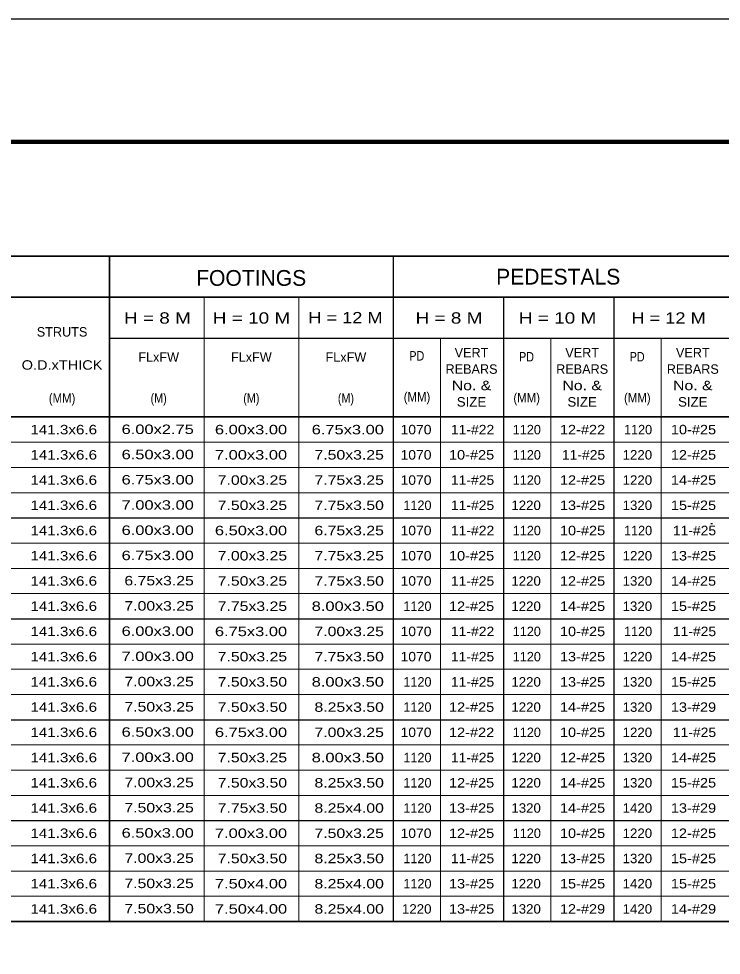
# Model space of a CAD drawing. Extents: x 312601.858 to 312602.699, y 144420.109 to 144420.703.
# Drawn here: x 312602.2619 to 312602.4847, y 144420.4063 to 144420.7033 of the extents above; entities that cross this region are included whole.
import ezdxf
from ezdxf.enums import TextEntityAlignment as Align

# ---------------------------------------------------------------- set-up
doc = ezdxf.new("R2010")
doc.units = 0
doc.header["$LTSCALE"] = 0.0012
doc.layers.add('1', color=7, linetype='Continuous', lineweight=13)
doc.layers.add('39', color=7, linetype='Continuous', lineweight=35)

msp = doc.modelspace()

# ---------------------------------------------------------------- linework, layer by layer
at = {"layer": '1', "lineweight": 35}
for p, q in [((312601.9277, 144420.628), (312602.6681, 144420.628)), ((312602.2907, 144420.417), (312602.2907, 144420.628)), ((312601.9607, 144420.615), (312602.6357, 144420.615)), ((312601.9277, 144420.577), (312602.6681, 144420.577)), ((312601.9277, 144420.417), (312602.6681, 144420.417))]:
    msp.add_line(p, q, dxfattribs=at)
at = {"layer": '1', "lineweight": 25}
for p, q in [((312602.3807, 144420.417), (312602.3807, 144420.628)), ((312602.4157, 144420.417), (312602.4157, 144420.615)), ((312602.4507, 144420.417), (312602.4507, 144420.615)), ((312602.2907, 144420.602), (312602.6357, 144420.602)), ((312601.9609, 144420.545), (312602.6357, 144420.545)), ((312602.4814, 144420.5432), (312602.4819, 144420.5432)), ((312601.9609, 144420.513), (312602.6357, 144420.513)), ((312601.9609, 144420.481), (312602.6357, 144420.481)), ((312601.9609, 144420.449), (312602.6357, 144420.449))]:
    msp.add_line(p, q, dxfattribs=at)
at = {"layer": '1'}
for p, q in [((312602.3207, 144420.417), (312602.3207, 144420.615)), ((312602.3507, 144420.417), (312602.3507, 144420.615)), ((312602.3957, 144420.417), (312602.3957, 144420.602)), ((312602.4307, 144420.417), (312602.4307, 144420.602)), ((312602.4657, 144420.417), (312602.4657, 144420.602)), ((312601.9607, 144420.569), (312602.6357, 144420.569)), ((312601.9609, 144420.561), (312602.6357, 144420.561)), ((312601.9609, 144420.553), (312602.6357, 144420.553)), ((312601.9609, 144420.537), (312602.6357, 144420.537)), ((312601.9609, 144420.529), (312602.6357, 144420.529)), ((312601.9609, 144420.521), (312602.6357, 144420.521)), ((312601.9609, 144420.505), (312602.6357, 144420.505)), ((312601.9609, 144420.497), (312602.6357, 144420.497)), ((312601.9609, 144420.489), (312602.6357, 144420.489)), ((312601.9609, 144420.473), (312602.6357, 144420.473)), ((312601.9609, 144420.465), (312602.6357, 144420.465)), ((312601.9609, 144420.457), (312602.6357, 144420.457)), ((312601.9609, 144420.441), (312602.6357, 144420.441)), ((312601.9609, 144420.433), (312602.6357, 144420.433)), ((312601.9609, 144420.425), (312602.6357, 144420.425))]:
    msp.add_line(p, q, dxfattribs=at)
at = {"layer": '39', "lineweight": 25}
msp.add_line((312601.8579, 144420.7033), (312602.6989, 144420.7033), dxfattribs=at)
at = {"layer": '39', "lineweight": 158}
msp.add_lwpolyline([(312601.9089, 144420.1245), (312601.9089, 144420.6643), (312602.6839, 144420.6643)], dxfattribs=at)

# ---------------------------------------------------------------- texts
at = {"layer": '1'}
for s, height, p in [('FOOTINGS', 0.005, (312602.3356, 144420.6186)), ('PEDESTALS', 0.005, (312602.433, 144420.619)), ('STRUTS', 0.003, (312602.2756, 144420.6025)), ('VERT', 0.003, (312602.4055, 144420.5959)), ('VERT', 0.003, (312602.4406, 144420.5959)), ('VERT', 0.003, (312602.4757, 144420.5959)), ('FLxFW', 0.003, (312602.30625, 144420.5945)), ('FLxFW', 0.003, (312602.33565, 144420.5945)), ('FLxFW', 0.003, (312602.36565, 144420.5945)), ('REBARS', 0.003, (312602.4055, 144420.5907)), ('REBARS', 0.003, (312602.4406, 144420.5907)), ('REBARS', 0.003, (312602.4757, 144420.5907))]:
    msp.add_text(s, height=height, dxfattribs=at).set_placement(p, align=Align.CENTER)
for s, height, width, p in [('H = 8 M', 0.0036, 1.25, (312602.30585, 144420.6066)), ('H = 10 M', 0.0036, 1.25, (312602.3357, 144420.6066)), ('H = 12 M', 0.0036, 1.2, (312602.3655, 144420.6067)), ('H = 8 M', 0.0036, 1.25, (312602.39835, 144420.6066)), ('H = 10 M', 0.0036, 1.25, (312602.4328, 144420.6066)), ('H = 12 M', 0.0036, 1.2, (312602.468, 144420.6066)), ('PD', 0.003, 0.85, (312602.38815, 144420.5949)), ('PD', 0.003, 0.85, (312602.42295, 144420.5946)), ('PD', 0.003, 0.85, (312602.45805, 144420.5946)), ('O.D.xTHICK', 0.003, 1.15, (312602.2756, 144420.592)), ('No. &', 0.003, 1.25, (312602.4055, 144420.5855)), ('No. &', 0.003, 1.25, (312602.4406, 144420.5855)), ('No. &', 0.003, 1.25, (312602.4757, 144420.5855)), ('(MM)', 0.003, 0.9, (312602.2756, 144420.5815)), ('(M)', 0.003, 0.85, (312602.30625, 144420.5815)), ('(M)', 0.003, 0.85, (312602.33565, 144420.5815)), ('(M)', 0.003, 0.85, (312602.36565, 144420.5815)), ('(MM)', 0.003, 0.9, (312602.3882, 144420.5819)), ('SIZE', 0.003, 1.05, (312602.4055, 144420.5803)), ('(MM)', 0.003, 0.9, (312602.423, 144420.5816)), ('SIZE', 0.003, 1.05, (312602.4406, 144420.5803)), ('(MM)', 0.003, 0.9, (312602.4581, 144420.5816)), ('SIZE', 0.003, 1.05, (312602.4757, 144420.5803))]:
    msp.add_text(s, height=height, dxfattribs=dict(at, width=width)).set_placement(p, align=Align.CENTER)
for s, width, p in [('141.3x6.6', 1.2, (312602.2867, 144420.5715)), ('6.00x2.75', 1.3, (312602.3174, 144420.5716)), ('6.00x3.00', 1.3, (312602.347, 144420.5715)), ('6.75x3.00', 1.3, (312602.3777, 144420.5715)), ('1070', 1.1, (312602.3928, 144420.5715)), ('11-#22', 1.1, (312602.4127, 144420.5715)), ('12-#22', 1.15, (312602.4479, 144420.5715)), ('10-#25', 1.15, (312602.4831, 144420.5715)), ('141.3x6.6', 1.2, (312602.2867, 144420.5635)), ('6.50x3.00', 1.3, (312602.3174, 144420.5636)), ('7.00x3.00', 1.3, (312602.347, 144420.5635)), ('7.50x3.25', 1.25, (312602.3777, 144420.5635)), ('1070', 1.1, (312602.3928, 144420.5635)), ('10-#25', 1.15, (312602.4127, 144420.5635)), ('11-#25', 1.1, (312602.4479, 144420.5635)), ('1220', 1.05, (312602.4628, 144420.5635)), ('12-#25', 1.15, (312602.4831, 144420.5635)), ('141.3x6.6', 1.2, (312602.2867, 144420.5555)), ('6.75x3.00', 1.3, (312602.3174, 144420.5556)), ('7.00x3.25', 1.25, (312602.347, 144420.5555)), ('7.75x3.25', 1.25, (312602.3777, 144420.5555)), ('1070', 1.1, (312602.3928, 144420.5555)), ('11-#25', 1.1, (312602.4127, 144420.5555)), ('12-#25', 1.15, (312602.4479, 144420.5555)), ('1220', 1.05, (312602.4628, 144420.5555)), ('14-#25', 1.15, (312602.4831, 144420.5555)), ('7.00x3.00', 1.3, (312602.3174, 144420.5476)), ('141.3x6.6', 1.2, (312602.2867, 144420.5475)), ('7.50x3.25', 1.25, (312602.347, 144420.5475)), ('7.75x3.50', 1.25, (312602.3777, 144420.5475)), ('11-#25', 1.1, (312602.4127, 144420.5475)), ('1220', 1.05, (312602.4275, 144420.5475)), ('13-#25', 1.15, (312602.4479, 144420.5475)), ('1320', 1.05, (312602.4628, 144420.5475)), ('15-#25', 1.15, (312602.4831, 144420.5475)), ('141.3x6.6', 1.2, (312602.2867, 144420.5395)), ('6.00x3.00', 1.3, (312602.3174, 144420.5396)), ('6.50x3.00', 1.3, (312602.347, 144420.5395)), ('6.75x3.25', 1.25, (312602.3777, 144420.5395)), ('1070', 1.1, (312602.3928, 144420.5395)), ('11-#22', 1.1, (312602.4127, 144420.5395)), ('10-#25', 1.15, (312602.4479, 144420.5395)), ('11-#25', 1.1, (312602.4831, 144420.5395)), ('141.3x6.6', 1.2, (312602.2867, 144420.5315)), ('6.75x3.00', 1.3, (312602.3174, 144420.5316)), ('7.00x3.25', 1.25, (312602.347, 144420.5315)), ('7.75x3.25', 1.25, (312602.3777, 144420.5315)), ('1070', 1.1, (312602.3928, 144420.5315)), ('10-#25', 1.15, (312602.4127, 144420.5315)), ('12-#25', 1.15, (312602.4479, 144420.5315)), ('1220', 1.05, (312602.4628, 144420.5315)), ('13-#25', 1.15, (312602.4831, 144420.5315)), ('141.3x6.6', 1.2, (312602.2867, 144420.5235)), ('6.75x3.25', 1.25, (312602.3174, 144420.5236)), ('7.50x3.25', 1.25, (312602.347, 144420.5235)), ('7.75x3.50', 1.25, (312602.3777, 144420.5235)), ('1070', 1.1, (312602.3928, 144420.5235)), ('11-#25', 1.1, (312602.4127, 144420.5235)), ('1220', 1.05, (312602.4275, 144420.5235)), ('12-#25', 1.15, (312602.4479, 144420.5235)), ('1320', 1.05, (312602.4628, 144420.5235)), ('14-#25', 1.15, (312602.4831, 144420.5235)), ('141.3x6.6', 1.2, (312602.2867, 144420.5155)), ('7.00x3.25', 1.25, (312602.3174, 144420.5156)), ('7.75x3.25', 1.25, (312602.347, 144420.5155)), ('8.00x3.50', 1.3, (312602.3777, 144420.5155)), ('12-#25', 1.15, (312602.4127, 144420.5155)), ('1220', 1.05, (312602.4275, 144420.5155)), ('14-#25', 1.15, (312602.4479, 144420.5155)), ('1320', 1.05, (312602.4628, 144420.5155)), ('15-#25', 1.15, (312602.4831, 144420.5155)), ('141.3x6.6', 1.2, (312602.2867, 144420.5075)), ('6.00x3.00', 1.3, (312602.3174, 144420.5076)), ('6.75x3.00', 1.3, (312602.347, 144420.5075)), ('7.00x3.25', 1.25, (312602.3777, 144420.5075)), ('1070', 1.1, (312602.3928, 144420.5075)), ('11-#22', 1.1, (312602.4127, 144420.5075)), ('10-#25', 1.15, (312602.4479, 144420.5075)), ('11-#25', 1.1, (312602.4831, 144420.5075)), ('141.3x6.6', 1.2, (312602.2867, 144420.4995)), ('7.00x3.00', 1.3, (312602.3174, 144420.4996)), ('7.50x3.25', 1.25, (312602.347, 144420.4995)), ('7.75x3.50', 1.25, (312602.3777, 144420.4995)), ('1070', 1.1, (312602.3928, 144420.4995)), ('11-#25', 1.1, (312602.4127, 144420.4995)), ('13-#25', 1.15, (312602.4479, 144420.4995)), ('1220', 1.05, (312602.4628, 144420.4995)), ('14-#25', 1.15, (312602.4831, 144420.4995)), ('141.3x6.6', 1.2, (312602.2867, 144420.4915)), ('7.00x3.25', 1.25, (312602.3174, 144420.4916)), ('7.50x3.50', 1.25, (312602.347, 144420.4915)), ('8.00x3.50', 1.3, (312602.3777, 144420.4915)), ('11-#25', 1.1, (312602.4127, 144420.4915)), ('1220', 1.05, (312602.4275, 144420.4915)), ('13-#25', 1.15, (312602.4479, 144420.4915)), ('1320', 1.05, (312602.4628, 144420.4915)), ('15-#25', 1.15, (312602.4831, 144420.4915)), ('141.3x6.6', 1.2, (312602.2867, 144420.4835)), ('7.50x3.25', 1.25, (312602.3174, 144420.4836)), ('7.50x3.50', 1.25, (312602.347, 144420.4835)), ('8.25x3.50', 1.25, (312602.3777, 144420.4835)), ('12-#25', 1.15, (312602.4127, 144420.4835)), ('1220', 1.05, (312602.4275, 144420.4835)), ('14-#25', 1.15, (312602.4479, 144420.4835)), ('1320', 1.05, (312602.4628, 144420.4835)), ('13-#29', 1.15, (312602.4831, 144420.4835)), ('141.3x6.6', 1.2, (312602.2867, 144420.4755)), ('6.50x3.00', 1.3, (312602.3174, 144420.4756)), ('6.75x3.00', 1.3, (312602.347, 144420.4755)), ('7.00x3.25', 1.25, (312602.3777, 144420.4755)), ('1070', 1.1, (312602.3928, 144420.4755)), ('12-#22', 1.15, (312602.4127, 144420.4755)), ('10-#25', 1.15, (312602.4479, 144420.4755)), ('1220', 1.05, (312602.4628, 144420.4755)), ('11-#25', 1.1, (312602.4831, 144420.4755)), ('141.3x6.6', 1.2, (312602.2867, 144420.4675)), ('7.00x3.00', 1.3, (312602.3174, 144420.4676)), ('7.50x3.25', 1.25, (312602.347, 144420.4675)), ('8.00x3.50', 1.3, (312602.3777, 144420.4675)), ('11-#25', 1.1, (312602.4127, 144420.4675)), ('1220', 1.05, (312602.4275, 144420.4675)), ('12-#25', 1.15, (312602.4479, 144420.4675)), ('1320', 1.05, (312602.4628, 144420.4675)), ('14-#25', 1.15, (312602.4831, 144420.4675)), ('141.3x6.6', 1.2, (312602.2867, 144420.4595)), ('7.00x3.25', 1.25, (312602.3174, 144420.4596)), ('7.50x3.50', 1.25, (312602.347, 144420.4595)), ('8.25x3.50', 1.25, (312602.3777, 144420.4595)), ('12-#25', 1.15, (312602.4127, 144420.4595)), ('1220', 1.05, (312602.4275, 144420.4595)), ('14-#25', 1.15, (312602.4479, 144420.4595)), ('1320', 1.05, (312602.4628, 144420.4595)), ('15-#25', 1.15, (312602.4831, 144420.4595)), ('141.3x6.6', 1.2, (312602.2867, 144420.4515)), ('7.50x3.25', 1.25, (312602.3174, 144420.4516)), ('7.75x3.50', 1.25, (312602.347, 144420.4515)), ('8.25x4.00', 1.25, (312602.3777, 144420.4515)), ('13-#25', 1.15, (312602.4127, 144420.4515)), ('1320', 1.05, (312602.4275, 144420.4515)), ('14-#25', 1.15, (312602.4479, 144420.4515)), ('1420', 1.05, (312602.4628, 144420.4515)), ('13-#29', 1.15, (312602.4831, 144420.4515)), ('6.50x3.00', 1.3, (312602.3174, 144420.4436)), ('141.3x6.6', 1.2, (312602.2867, 144420.4435)), ('7.00x3.00', 1.3, (312602.347, 144420.4435)), ('7.50x3.25', 1.25, (312602.3777, 144420.4435)), ('1070', 1.1, (312602.3928, 144420.4435)), ('12-#25', 1.15, (312602.4127, 144420.4435)), ('10-#25', 1.15, (312602.4479, 144420.4435)), ('1220', 1.05, (312602.4628, 144420.4435)), ('12-#25', 1.15, (312602.4831, 144420.4435)), ('141.3x6.6', 1.2, (312602.2867, 144420.4355)), ('7.00x3.25', 1.25, (312602.3174, 144420.4356)), ('7.50x3.50', 1.25, (312602.347, 144420.4355)), ('8.25x3.50', 1.25, (312602.3777, 144420.4355)), ('11-#25', 1.1, (312602.4127, 144420.4355)), ('1220', 1.05, (312602.4275, 144420.4355)), ('13-#25', 1.15, (312602.4479, 144420.4355)), ('1320', 1.05, (312602.4628, 144420.4355)), ('15-#25', 1.15, (312602.4831, 144420.4355)), ('141.3x6.6', 1.2, (312602.2867, 144420.4275)), ('7.50x3.25', 1.25, (312602.3174, 144420.4276)), ('7.50x4.00', 1.3, (312602.347, 144420.4275)), ('8.25x4.00', 1.25, (312602.3777, 144420.4275)), ('13-#25', 1.15, (312602.4127, 144420.4275)), ('1220', 1.05, (312602.4275, 144420.4275)), ('15-#25', 1.15, (312602.4479, 144420.4275)), ('1420', 1.05, (312602.4628, 144420.4275)), ('15-#25', 1.15, (312602.4831, 144420.4275)), ('141.3x6.6', 1.2, (312602.2867, 144420.4195)), ('7.50x3.50', 1.25, (312602.3174, 144420.4196)), ('7.50x4.00', 1.3, (312602.347, 144420.4195)), ('8.25x4.00', 1.25, (312602.3777, 144420.4195)), ('1220', 1.05, (312602.3928, 144420.4195)), ('13-#25', 1.15, (312602.4127, 144420.4195)), ('1320', 1.05, (312602.4275, 144420.4195)), ('12-#29', 1.15, (312602.4479, 144420.4195)), ('1420', 1.05, (312602.4628, 144420.4195)), ('14-#29', 1.15, (312602.4831, 144420.4195))]:
    msp.add_text(s, height=0.003, dxfattribs=dict(at, width=width)).set_placement(p, align=Align.RIGHT)
for p in [(312602.4275, 144420.5715), (312602.4628, 144420.5715), (312602.4275, 144420.5635), (312602.4275, 144420.5555), (312602.3928, 144420.5475), (312602.4275, 144420.5395), (312602.4628, 144420.5395), (312602.4275, 144420.5315), (312602.3928, 144420.5155), (312602.4275, 144420.5075), (312602.4628, 144420.5075), (312602.4275, 144420.4995), (312602.3928, 144420.4915), (312602.3928, 144420.4835), (312602.4275, 144420.4755), (312602.3928, 144420.4675), (312602.3928, 144420.4595), (312602.3928, 144420.4515), (312602.4275, 144420.4435), (312602.3928, 144420.4355), (312602.3928, 144420.4275)]:
    msp.add_text('1120', height=0.003, dxfattribs=at).set_placement(p, align=Align.RIGHT)

doc.saveas('drawing.dxf')
